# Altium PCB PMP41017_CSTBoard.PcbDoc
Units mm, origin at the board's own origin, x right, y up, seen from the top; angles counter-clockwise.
Board outline 22.5 x 35.13 mm, 4 copper layers (Top Layer, Layer 1, Layer 2, Bottom Layer), stack 1.926 mm thick; 6 components, 8 nets, 28 pads, 303 vias.
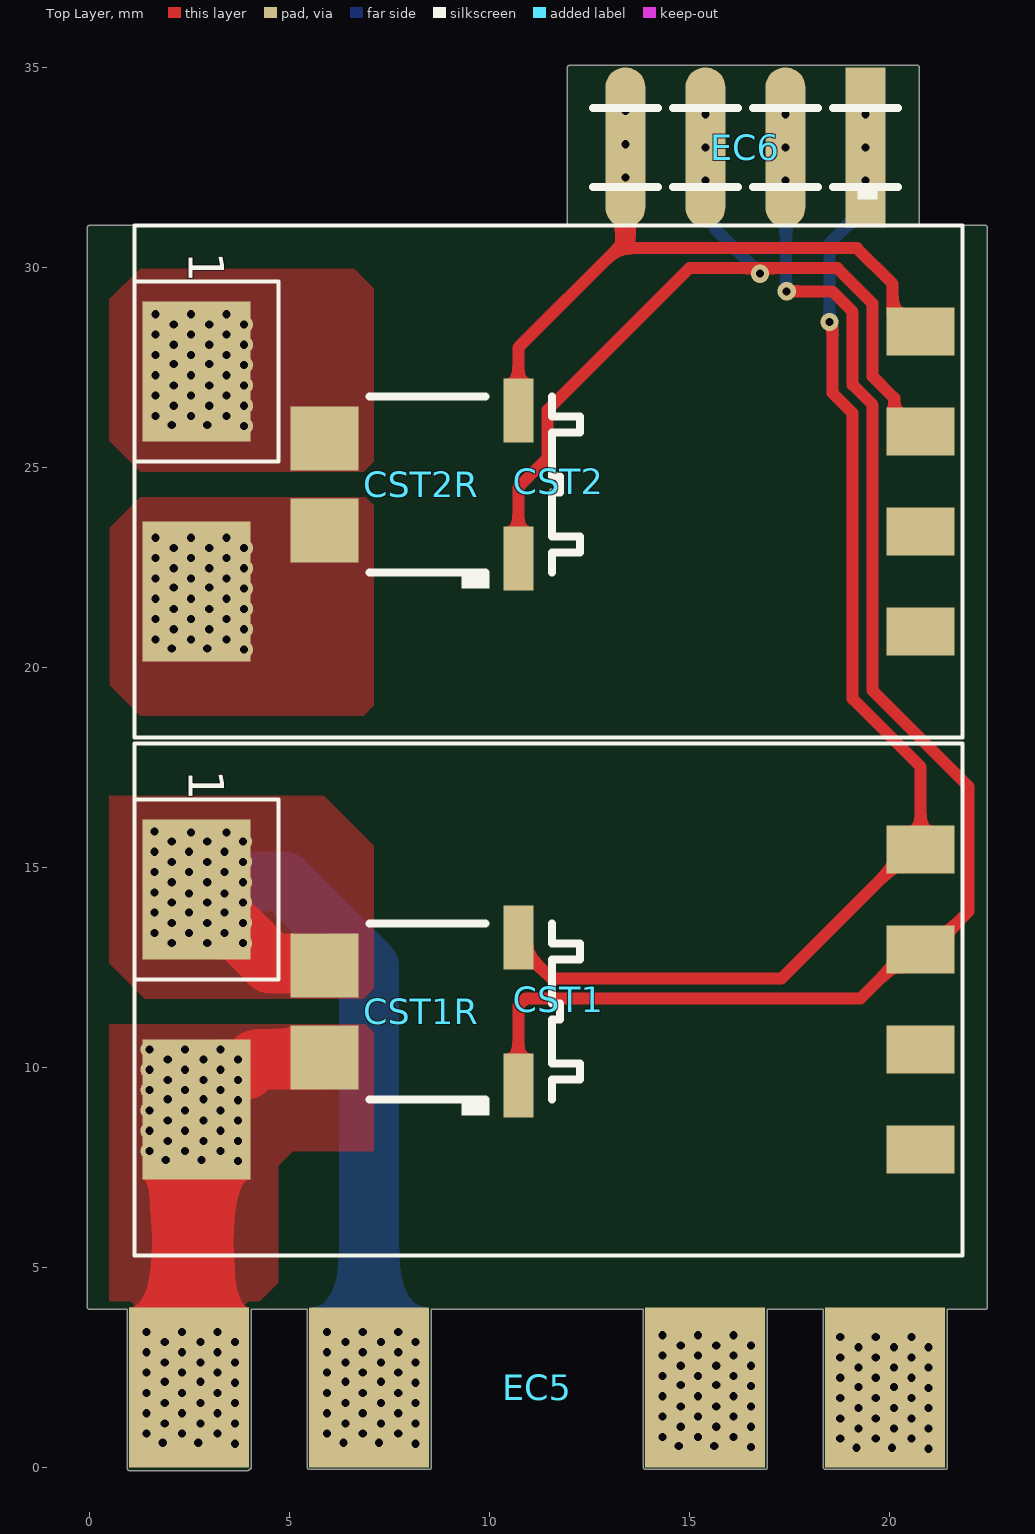
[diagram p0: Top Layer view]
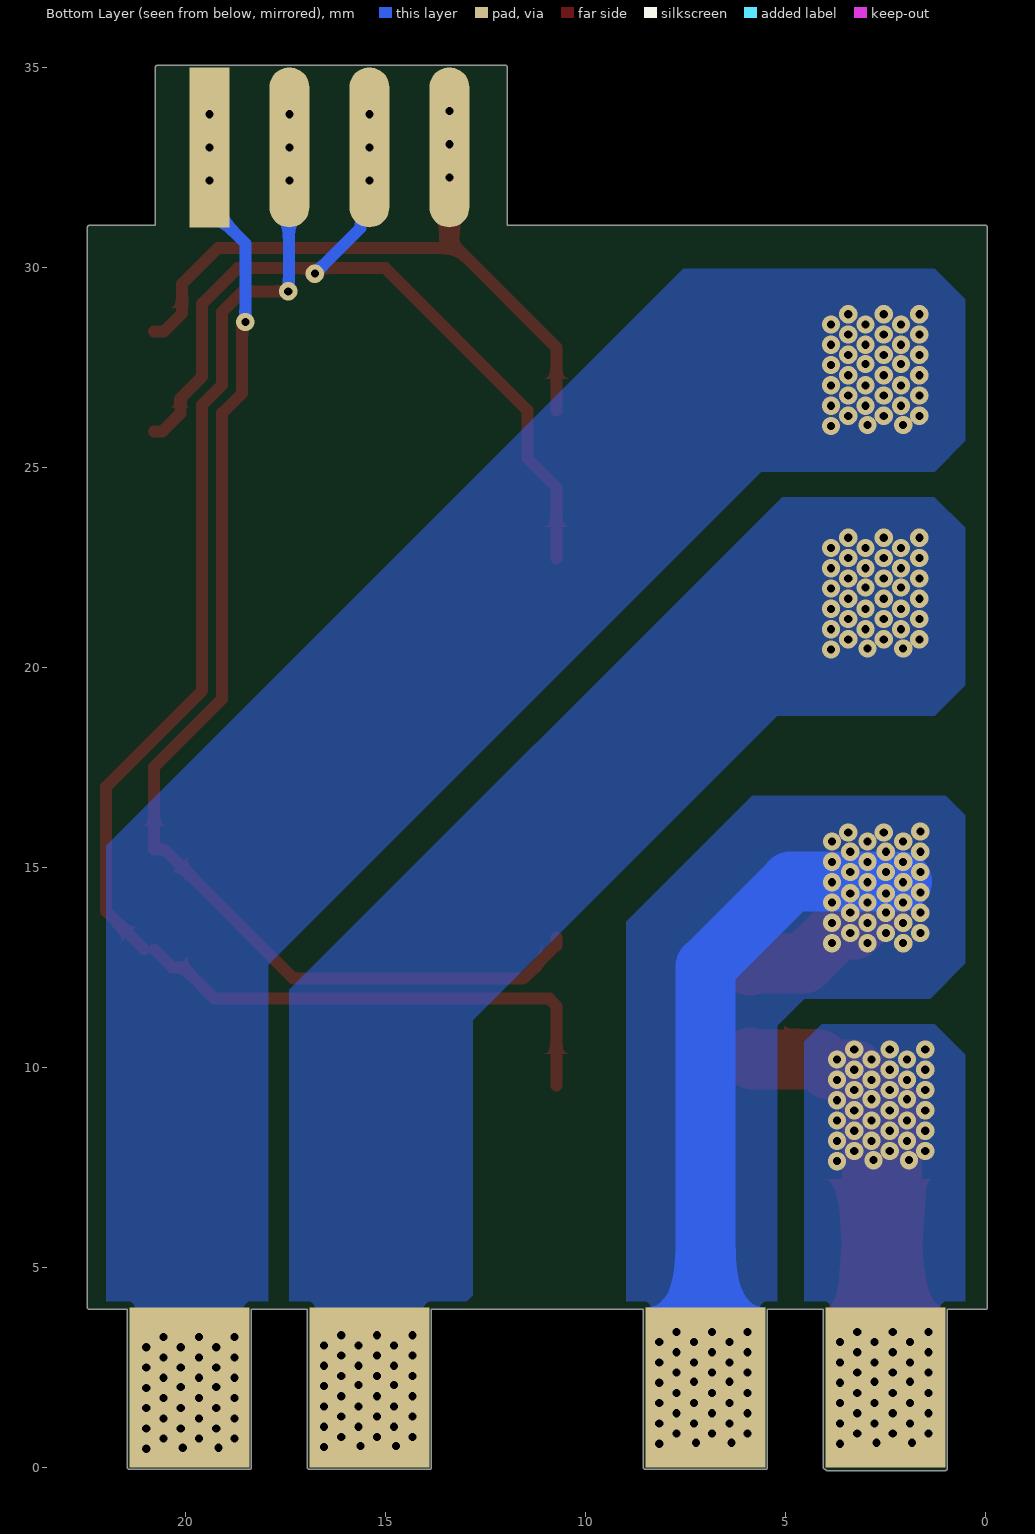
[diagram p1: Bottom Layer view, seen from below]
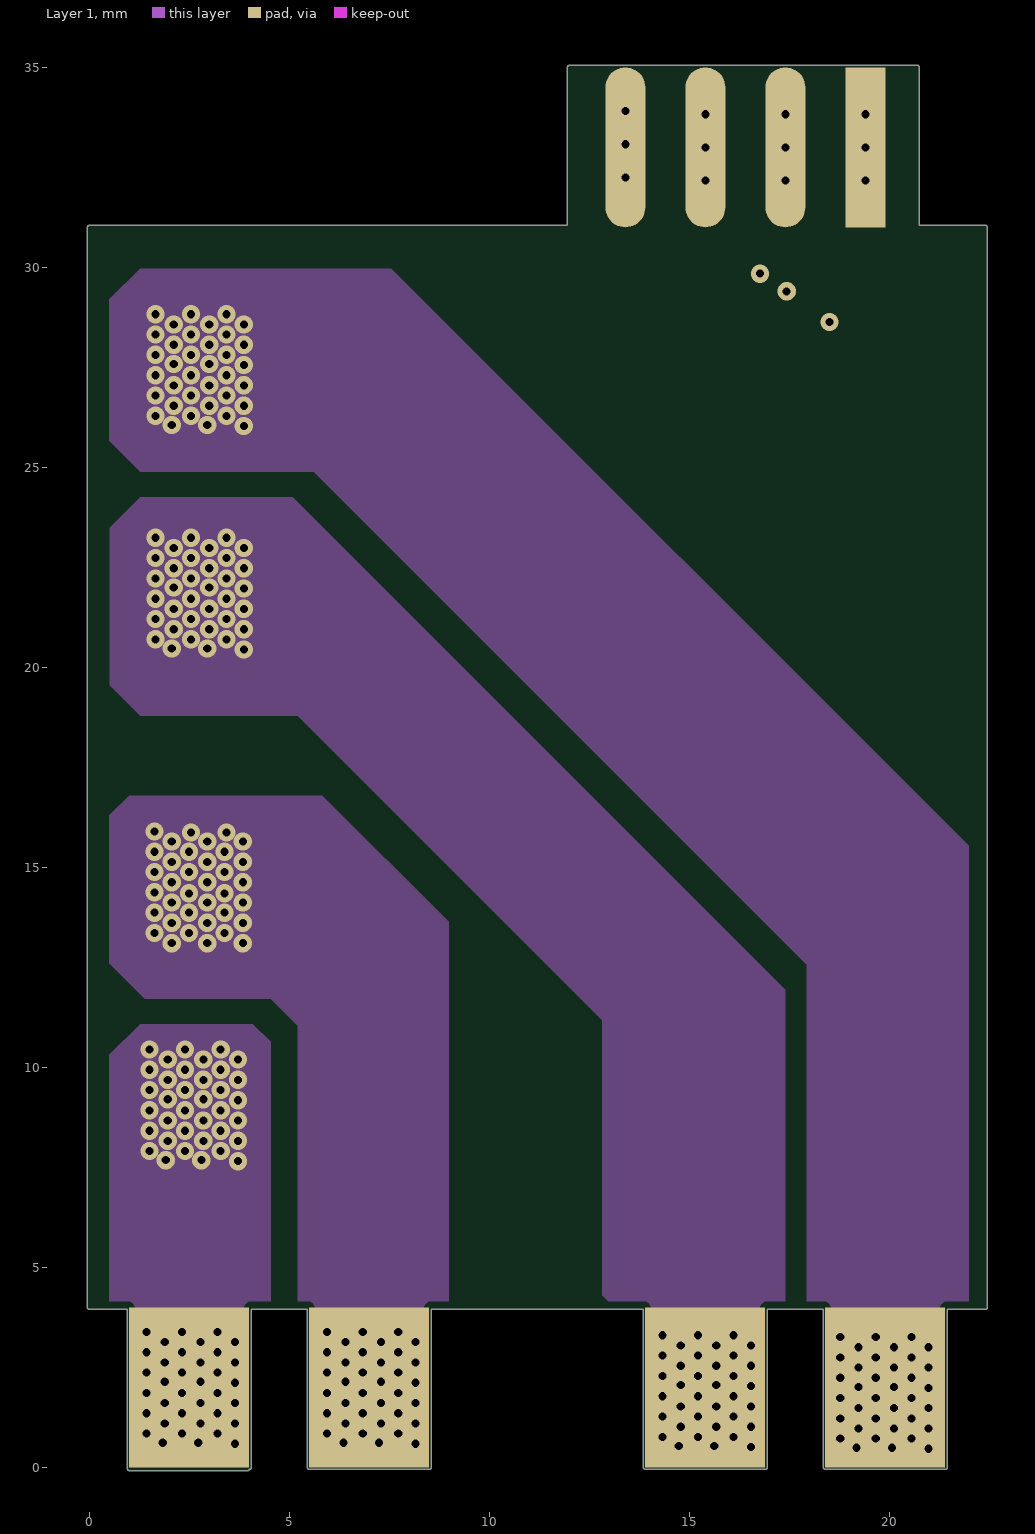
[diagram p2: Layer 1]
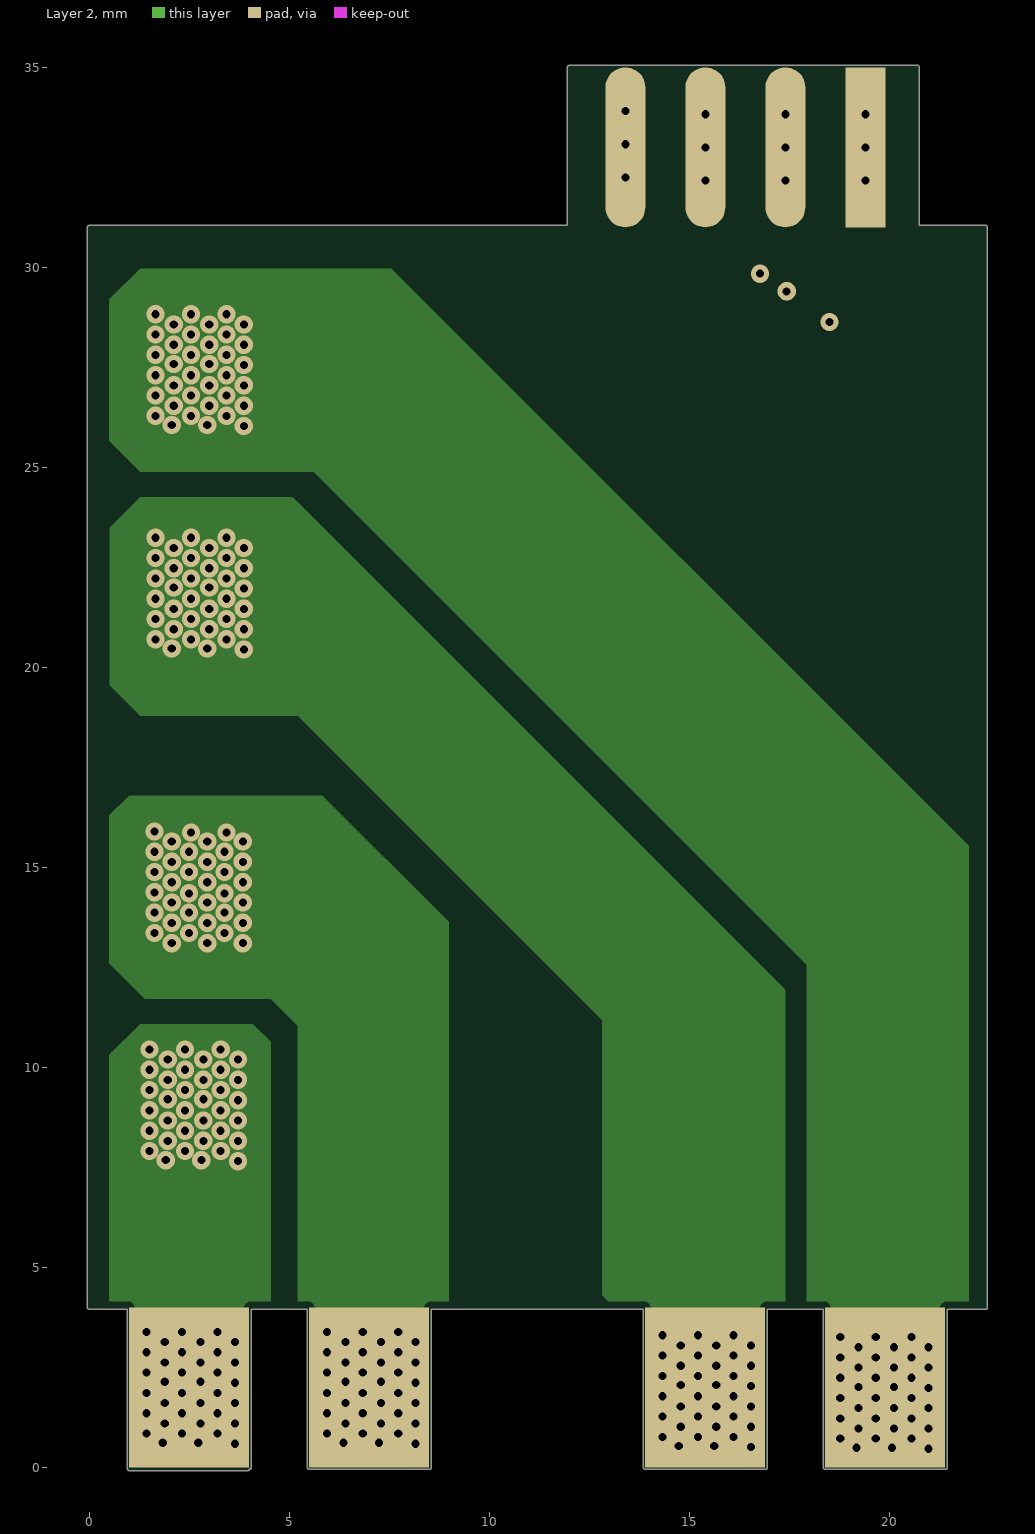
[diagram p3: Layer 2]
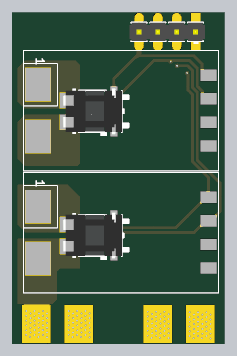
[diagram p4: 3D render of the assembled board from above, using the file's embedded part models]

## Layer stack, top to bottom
Top Solder: solder mask 0.0102, Solder Resist, Dk 3.5
Top Layer: signal copper 0.07
Dielectric 1: prepreg 0.0711, PP-006, Dk 4.1
Layer 1: signal copper 0.07
Dielectric1: core 1.5037, FR-4 High Tg, Dk 4.8
Layer 2: signal copper 0.07
Dielectric 2: prepreg 0.0711, PP-006, Dk 4.1
Bottom Layer: signal copper 0.07
Bottom Solder: solder mask 0.0102, Solder Resist, Dk 3.5

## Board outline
1,-0.079 3.957,-0.079 ccw(c3.957,-0.029) 4.003,-0.05 ccw(c4,0) 4.05,0 4.05,3.95 5.45,3.95 5.45,0 ccw(c5.5,0) 5.525,-0.044 ccw(c5.55,0) 5.55,-0.05 8.5,-0.05 ccw(c8.5,0) 8.55,0 8.55,3.95 13.85,3.95 13.85,0 ccw(c13.9,0) 13.9,-0.05 16.9,-0.05 ccw(c16.9,0) 16.95,0 16.95,3.95 18.35,3.95 18.35,0 ccw(c18.4,0) 18.4,-0.05 21.4,-0.05 ccw(c21.4,0) 21.45,0 21.45,3.95 22.4,3.95 ccw(c22.4,4) 22.45,4 22.45,31 ccw(c22.4,31) 22.4,31.05 20.75,31.05 20.75,35 ccw(c20.7,35) 20.7,35.05 12,35.05 ccw(c12,35) 11.95,35 11.95,31.05 0,31.05 ccw(c0,31) -0.05,31 -0.05,4 ccw(c0,4) 0,3.95 0.95,3.95 0.95,-0.029 ccw(c1,-0.029)

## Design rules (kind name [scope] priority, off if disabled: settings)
AcuteAngle [All] p1: minimum=4.50000000000000E+0001 checktracksonly=FALSE
AssemblyTestPointUsage [All] p1: valid=2
BoardOutlineClearance BoardOutlineClearance_MountingHoles [OnCopper and InComponentClass('Mounting Holes')] p1: gap=0.2 ignorepadtopadclearanceinfootprint=FALSE
BoardOutlineClearance BoardOutlineClearance_Poly [OnCopper and IsPoly] p2: gap=0.2 ignorepadtopadclearanceinfootprint=FALSE
BoardOutlineClearance [OnCopper and Not InComponentClass('Logo') and not InComponentClass('FiducialMark') and not InRegion(1000,500,4000,800) and not InPoly] p3: gap=0.2 ignorepadtopadclearanceinfootprint=FALSE
Clearance Clearance_Keepouts [((IsTrack Or IsArc) And Not InPoly) And IsFree and IsKeepOut vs ((IsTrack Or IsArc) And Not InPoly) And IsFree and IsKeepOut] p1: gap=0 ignorepadtopadclearanceinfootprint=FALSE
Clearance Clearance_Poly [InPolygon] p2: gap=0.254 ignorepadtopadclearanceinfootprint=TRUE
Clearance Clearance_FiducialMark [IsKeepOut and InComponentClass('FiducialMark') vs IsPad and InComponentClass('FiducialMark')] p3: gap=0 ignorepadtopadclearanceinfootprint=FALSE
Clearance [All] p4: gap=0.2 ignorepadtopadclearanceinfootprint=TRUE
ComponentClearance ComponentClearance_MountingHoles_FiducialMarks [InComponentClass('Mounting Holes') vs InComponentClass('FiducialMark')] p1 off: gap=1.27 collisioncheckmode=3 verticalgap=0.254 showdistances=FALSE
ComponentClearance ComponentClearance_Shunt [InComponentClass('Header') vs InComponentClass('Shunt')] p2 off: gap=0 collisioncheckmode=3 verticalgap=0 showdistances=FALSE
ComponentClearance ComponentClearance_Logo [InComponentClass('Logo')] p3 off: gap=0.762 collisioncheckmode=3 verticalgap=0.254 showdistances=FALSE
ComponentClearance ComponentClearance_ScrewToNut [(HasFootprint('NY PMS 440 0025 PH')) vs (HasFootprint('Keystone_1902C'))] p4 off: gap=0.127 collisioncheckmode=3 verticalgap=0.254 showdistances=FALSE
ComponentClearance ComponentClearance_MountingHoles [InComponentClass('Mounting Holes')] p5 off: gap=2.54 collisioncheckmode=3 verticalgap=2540 showdistances=FALSE
ComponentClearance ComponentClearance_SmallPassives [HasFootprint('0201*') or HasFootprint('0402*') or HasFootprint('0508') or HasFootprint('0603*') or HasFootprint('0612') or HasFootprint('0805*') or HasFootprint('0815*') or HasFootprint('0830*') or HasFootprint('1206*') or HasFootprint('1210*') or HasFootprint('1808*') or HasFootprint('1812*') or HasFootprint('1825*') or HasFootprint('2010*') or HasFootprint('2220*') or HasFootprint('2225*') or HasFootprint('2512*') or HasFootprint('2728*') or HasFootprint('3518*') vs HasFootprint('0201*') or HasFootprint('0402*') or HasFootprint('0508') or HasFootprint('0603*') or HasFootprint('0612') or HasFootprint('0805*') or HasFootprint('0815*') or HasFootprint('0830*') or HasFootprint('1206*') or HasFootprint('1210*') or HasFootprint('1808*') or HasFootprint('1812*') or HasFootprint('1825*') or HasFootprint('2010*') or HasFootprint('2220*') or HasFootprint('2225*') or HasFootprint('2512*') or HasFootprint('2728*') or HasFootprint('3518*')] p6 off: gap=0.38 collisioncheckmode=3 verticalgap=0.254 showdistances=FALSE
ComponentClearance ComponentClearance_THtoSMT [IsThruComponent vs IsSMTComponent] p7 off: gap=0.762 collisioncheckmode=3 verticalgap=0.762 showdistances=FALSE
ComponentClearance ComponentClearance_THtoTH [IsThruComponent vs IsThruComponent] p8 off: gap=0.508 collisioncheckmode=3 verticalgap=0.762 showdistances=FALSE
ComponentClearance [All] p9 off: gap=0.508 collisioncheckmode=3 verticalgap=0.254 showdistances=FALSE
DiffPairsRouting [All] p1: maxlimit=2.54 minlimit=0.254 mostfreqgap=0.254 toplayer_minwidth=0.381 toplayer_maxwidth=0.381 toplayer_prefwidth=0.381 midlayer1_minwidth=0.381 midlayer1_maxwidth=0.381 midlayer1_prefwidth=0.381 midlayer2_minwidth=0.381 midlayer2_maxwidth=0.381 midlayer2_prefwidth=0.381 bottomlayer_minwidth=0.381 bottomlayer_maxwidth=0.381 bottomlayer_prefwidth=0.381 maxuncoupledlength=25.4
FabricationTestPointUsage TestPointUsage [All] p1: valid=2 allowmultiple=FALSE
FabricationTestpoint Testpoint [All] p1: side=3 testpointundercomponent=TRUE minsize=1.016 maxsize=2.54 preferedsize=1.524 minholesize=0 maxholesize=1.016 preferedholesize=0.813 testpointgrid=0.025 allowsidetop=TRUE allowsidebottom=TRUE usegrid=TRUE gridtolerance=0
FanoutControl Fanout_LCC [IsLCC] p1: bgadir=Out bgaviamode=Centered fanoutstyle=Auto fanoutdirection=Alternating viagrid=0.025 // Fanout_LCC (Default Rule)
FanoutControl Fanout_BGA [IsBGA] p2: bgadir=Out bgaviamode=Centered fanoutstyle=Auto fanoutdirection=Alternating viagrid=0.025 // Fanout_BGA (Default Rule)
FanoutControl Fanout_Default [All] p4: bgadir=Out bgaviamode=Centered fanoutstyle=Auto fanoutdirection=Alternating viagrid=0.025 // Fanout_Default (Default Rule)
FanoutControl Fanout_Small [(CompPinCount < 5)] p5: bgadir=Out bgaviamode=Centered fanoutstyle=Auto fanoutdirection=OutThenIn viagrid=0.025 // Fanout_Small (Default Rule)
Height [All] p1 off: minheight=0 maxheight=30 prefheight=12.7
HoleSize [All] p1: absolutevalues=TRUE maxlimit=6.375 minlimit=0.2 maxpercent=80.000 minpercent=20.000
MinimumAnnularRing MinimumAnnularRing_ThermalPadVias [IsVia and InAnyComponent] p1: minimumring=0.15
MinimumAnnularRing [All] p2: minimumring=0.2
MinimumSolderMaskSliver MinimumSolderMaskSliver_Logo [InComponentClass('Logo') vs InComponentClass('Logo')] p1: minsoldermaskwidth=0.018
MinimumSolderMaskSliver [All] p2: minsoldermaskwidth=0.1
PlaneConnect [All] p1: planeconnectstyle=Direct reliefexpansion=0.254 reliefentries=4 reliefconductorwidth=0.254 reliefairgap=0.254
PolygonConnect [All] p1: connectstyle=Direct reliefconductorwidth=0.254 reliefentries=4 polygonreliefangle="90 Angle" airgapwidth=0.254
RoutingVias ThermalPadVias [IsVia and InAnyComponent] p1: holewidth=0.2 width=0.5 viastyle="Through Hole" minholewidth=0.2 minwidth=0.5 maxholewidth=0.33 maxwidth=0.6
RoutingVias [All] p2: holewidth=0.3 width=0.5 viastyle="Through Hole" minholewidth=0.2 minwidth=0.61 maxholewidth=1.016 maxwidth=1.651
SilkToBoardRegionClearance [Not ((IsComment or IsDesignator) And (Hide <> 'False')) and not InRegion(1000,500,4000,800)] p1:
SilkToSilkClearance SilkToSilkClearance_Pb-FreeLogo [(HasFootprint('Pb-Free_Overlay_Medium') OR HasFootprint('Pb-Free_Overlay_Small')) vs (HasFootprint('Pb-Free_Overlay_Medium') OR HasFootprint('Pb-Free_Overlay_Small'))] p1: silktosilkclearance=0
SilkToSilkClearance [All] p2: silktosilkclearance=0.1
SilkToSolderMaskClearance SilkToComponentPadClearance [(IsPad or IsFill or IsRegion) and InAnycomponent] p1: minsilkscreentomaskgap=0.127 clearancetoexposedcopper=TRUE
SilkToSolderMaskClearance "Silk to Solder Mask Opening" [All] p2: minsilkscreentomaskgap=0.1 clearancetoexposedcopper=FALSE
SolderMaskExpansion [All] p1: expansion=0.05 istentingtop=FALSE
UnRoutedNet [All] p1: checkbadconnections=TRUE
Width [All] p1: maxlimit=2.54 minlimit=0.152 preferedwidth=0.254 checkconnectedcopper=TRUE
13 further rules are at their usual default settings.

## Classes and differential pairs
component class Header: EC6

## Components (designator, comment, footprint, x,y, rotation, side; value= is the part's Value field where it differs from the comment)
CST1 "PAS6322.050NLT" Pulse_PAS6322 11.731,11.7 r270 top locked
CST1R "CST7030-050LC" Coilcraft_CST7030 8.3,11.4 r180 top
CST2 "PAS6322.050NLT" Pulse_PAS6322 11.731,24.65 r270 top locked
CST2R "CST7030-050LC" Coilcraft_CST7030 8.3,24.575 r180 top
EC5 "Edge Finger" EC_CST 22.494,3.95 r180 top
EC6 "PTT-104-01-L-S" Samtec_PTT-104-01-x-S 16.4,33 r180 top locked

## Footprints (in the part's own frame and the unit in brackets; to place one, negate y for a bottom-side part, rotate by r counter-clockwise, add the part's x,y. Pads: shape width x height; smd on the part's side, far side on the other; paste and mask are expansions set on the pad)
Coilcraft_CST7030 [mm] "SMD, 4-Leads, Body 7x5.2mm"
  rect 0.75x1.6 smd: 1(-2.425,1.85) 2(-2.425,-1.85)
  rect 1.7x1.6 smd: 3(2.425,-1.15) 4(2.425,1.15)
  silkscreen extent -3.97,-2.2 1.3,2.6, body extent -3.97,-2.5 3.03,2.5, height 3
EC_CST [mm] "Edge connector of HB LLC GaN DC"
  rect 3x4 all layers, no hole: 1(2.6,1.95) 2(7.1,1.95) 3(15.5,1.95) 4(20,1.95)
Pulse_PAS6322 [mm]
  rect 3.5x2.7 smd: 1(-2.75,-9.05) 2(2.75,-9.05)
  rect 1.2x1.7 smd: 3(3.75,9.05) 4(1.25,9.05) 5(-1.25,9.05) 6(-3.75,9.05)
  silkscreen extent -6.4,-10.6 6.4,10.1
Samtec_PTT-104-01-x-S [mm] "Header, 2mm, 4x1, TH"
  rect 1x4 all layers, no hole: 1(-3,0)
  oval 1x4 all layers, no hole: 2(-1,0) 3(1,0) 4(3,0)
  silkscreen extent -3.81,-0.99 3.81,1.3, body extent -4,-0.99 4,0.99, height 4.7

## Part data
CST1 CST2: library part Coilcraft_CST7030, "Current Sense Transformer, 1100uH, SMT", Manufacturer=Pulse
CST1R CST2R: library part CMP-0030157-2, "Current Sense Transformer, 333uH, SMT", Manufacturer=Coilcraft
EC5: library part EC_CT, "Edge Finger of CT board"
EC6: library part CMP-0055572-1, "Header, 2mm, 4x1, Gold, TH", Color=Black, Current_A=2.9A, Manufacturer=Samtec

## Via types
v1: diameter 0.457, hole 0.203, Top Layer to Bottom Layer, tented both sides, 303 vias

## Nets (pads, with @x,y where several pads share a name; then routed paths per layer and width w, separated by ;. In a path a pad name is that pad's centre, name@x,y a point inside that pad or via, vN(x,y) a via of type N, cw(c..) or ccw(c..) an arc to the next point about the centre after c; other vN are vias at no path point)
CT1p_in: CST1.2 CST1R.4 EC5.4 | length 11
  Top Layer w1.5: CST1.2@2.587,8.857 2.587,9.257 3.281,9.95 3.909,9.95 4.159,10.2 5.825,10.2 CST1R.4
  Top Layer w2: EC5.4 2.587,2.093 CST1.2@2.587,8.857
  other v1: 3.636,0.592 1.833,0.617 2.722,0.617 1.426,0.846 2.315,0.846 3.204,0.846 1.884,1.1 2.773,1.1 3.636,1.1 1.426,1.354 2.315,1.354 3.204,1.354 1.884,1.608 2.773,1.608 3.636,1.608 1.426,1.862 2.315,1.862 3.204,1.862 3.636,2.116 1.884,2.141 2.773,2.141 1.426,2.37 2.315,2.37 3.204,2.37 1.884,2.624 2.773,2.624 3.636,2.624 1.426,2.878 2.315,2.878 3.204,2.878 1.884,3.132 2.773,3.132 3.636,3.132 1.426,3.386 2.315,3.386 3.204,3.386 3.712,7.656 1.909,7.681 2.798,7.681 1.503,7.91 2.392,7.91 3.281,7.91 1.96,8.164 2.849,8.164 3.712,8.164 1.503,8.418 2.392,8.418 3.281,8.418 1.96,8.672 2.849,8.672 3.712,8.672 1.503,8.926 2.392,8.926 3.281,8.926 3.712,9.18 1.96,9.205 2.849,9.205 1.503,9.434 2.392,9.434 3.281,9.434 1.96,9.688 2.849,9.688 3.712,9.688 1.503,9.942 2.392,9.942 3.281,9.942 1.96,10.196 2.849,10.196 3.712,10.196 1.503,10.45 2.392,10.45 3.281,10.45
CT1p_out: CST1.1 CST1R.3 EC5.3 | length 20.1
  Top Layer w1.5: CST1.1@2.681,14.05 3.281,13.45 3.681,13.45 4.531,12.6 5.825,12.6 CST1R.3
  Bottom Layer w1.5: v1@2.083,14.643 4.869,14.643 6.994,12.518 EC5.3
  other v1: 8.153,0.592 6.35,0.617 7.239,0.617 5.944,0.846 6.833,0.846 7.722,0.846 6.401,1.1 7.29,1.1 8.153,1.1 5.944,1.354 6.833,1.354 7.722,1.354 6.401,1.608 7.29,1.608 8.153,1.608 5.944,1.862 6.833,1.862 7.722,1.862 8.153,2.116 6.401,2.141 7.29,2.141 5.944,2.37 6.833,2.37 7.722,2.37 6.401,2.624 7.29,2.624 8.153,2.624 5.944,2.878 6.833,2.878 7.722,2.878 6.401,3.132 7.29,3.132 8.153,3.132 5.944,3.386 6.833,3.386 7.722,3.386 2.057,13.106 2.946,13.106 3.835,13.106 1.626,13.36 2.489,13.36 3.378,13.36 2.057,13.614 2.946,13.614 3.835,13.614 1.626,13.868 2.489,13.868 3.378,13.868 2.057,14.122 2.946,14.122 3.835,14.122 2.489,14.351 3.378,14.351 1.626,14.376 2.057,14.63 2.946,14.63 3.835,14.63 1.626,14.884 2.489,14.884 3.378,14.884 2.057,15.138 2.946,15.138 3.835,15.138 1.626,15.392 2.489,15.392 3.378,15.392 2.057,15.646 2.946,15.646 3.835,15.646 2.54,15.875 3.429,15.875 1.626,15.9
CT1s_neg: CST1.5 CST1R.1 EC6.2 | length 35.6
  Top Layer w0.3: CST1R.1 10.725,11.541 10.901,11.717 19.273,11.717 20.056,12.5 20.331,12.5 CST1.5 ; v1(17.43,29.401) 18.568,29.401 19.081,28.888 19.081,27.066 19.581,26.566 19.581,19.42 21.981,17.02 21.981,13.9 CST1.5@21.031,12.95
  Bottom Layer w0.3: v1(17.4,33) v1(17.4,32.17) 17.415,32.155 17.415,29.416 v1(17.43,29.401)
  other v1: 17.4,33.829
CT1s_pos: CST1.6 CST1R.2 EC6.1 | length 30.8
  Top Layer w0.3: CST1R.2 10.725,13.05 11.558,12.217 17.297,12.217 20.081,15 20.531,15.45 CST1.6 20.781,17.513 19.081,19.213 19.081,26.358 18.581,26.858 18.581,28.515 18.502,28.594 v1(18.502,28.636)
  Bottom Layer w0.3: v1(18.502,28.636) 18.502,30.602 19.4,31.5 v1(19.4,33)
  other v1: 19.4,32.17 19.4,33.829
CT2p_in: CST2.1 CST2R.3 EC5.1
  other v1: 20.98,0.465 19.177,0.49 20.066,0.49 18.771,0.719 19.66,0.719 20.549,0.719 19.228,0.973 20.117,0.973 20.98,0.973 18.771,1.227 19.66,1.227 20.549,1.227 19.228,1.481 20.117,1.481 20.98,1.481 18.771,1.735 19.66,1.735 20.549,1.735 20.98,1.989 19.228,2.014 20.117,2.014 18.771,2.243 19.66,2.243 20.549,2.243 19.228,2.497 20.117,2.497 20.98,2.497 18.771,2.751 19.66,2.751 20.549,2.751 19.228,3.005 20.117,3.005 20.98,3.005 18.771,3.259 19.66,3.259 20.549,3.259 3.861,26.035 2.057,26.06 2.946,26.06 1.651,26.289 2.54,26.289 3.429,26.289 2.108,26.543 2.997,26.543 3.861,26.543 1.651,26.797 2.54,26.797 3.429,26.797 2.108,27.051 2.997,27.051 3.861,27.051 1.651,27.305 2.54,27.305 3.429,27.305 3.861,27.559 2.108,27.584 2.997,27.584 1.651,27.813 2.54,27.813 3.429,27.813 2.108,28.067 2.997,28.067 3.861,28.067 1.651,28.321 2.54,28.321 3.429,28.321 2.108,28.575 2.997,28.575 3.861,28.575 1.651,28.829 2.54,28.829 3.429,28.829
CT2p_out: CST2.2 CST2R.4 EC5.2
  other v1: 16.535,0.51 14.732,0.535 15.621,0.535 14.326,0.764 15.215,0.764 16.104,0.764 14.783,1.018 15.672,1.018 16.535,1.018 14.326,1.272 15.215,1.272 16.104,1.272 14.783,1.526 15.672,1.526 16.535,1.526 14.326,1.78 15.215,1.78 16.104,1.78 16.535,2.034 14.783,2.059 15.672,2.059 14.326,2.288 15.215,2.288 16.104,2.288 14.783,2.542 15.672,2.542 16.535,2.542 14.326,2.796 15.215,2.796 16.104,2.796 14.783,3.05 15.672,3.05 16.535,3.05 14.326,3.304 15.215,3.304 16.104,3.304 3.861,20.447 2.057,20.472 2.946,20.472 1.651,20.701 2.54,20.701 3.429,20.701 2.108,20.955 2.997,20.955 3.861,20.955 1.651,21.209 2.54,21.209 3.429,21.209 2.108,21.463 2.997,21.463 3.861,21.463 1.651,21.717 2.54,21.717 3.429,21.717 3.861,21.971 2.108,21.996 2.997,21.996 1.651,22.225 2.54,22.225 3.429,22.225 2.108,22.479 2.997,22.479 3.861,22.479 1.651,22.733 2.54,22.733 3.429,22.733 2.108,22.987 2.997,22.987 3.861,22.987 1.651,23.241 2.54,23.241 3.429,23.241
CT2s_neg: CST2.6 CST2R.2 EC6.4 | length 16.5
  Top Layer w0.3: CST2R.2 10.725,27.997 13.208,30.48 ; 13.4,30.672 13.208,30.48 ; CST2.6 20.531,28.4 20.081,28.85 20.081,29.587 19.188,30.48 13.208,30.48
  Top Layer w0.5: 13.4,30.672 EC6.4
  other v1: 13.4,32.25 13.4,33.079 13.4,33.909
CT2s_pos: CST2.5 CST2R.1 EC6.3 | length 21.5
  Top Layer w0.3: CST2R.1 10.725,24.504 11.45,25.229 11.45,26.431 14.999,29.98 16.764,29.98 18.696,29.98 19.581,29.096 19.581,27.273 20.124,26.73 20.124,26.35 20.574,25.9 CST2.5
  Bottom Layer w0.3: v1(15.4,33) 15.4,31.311 15.626,31.084 15.626,30.983 v1(16.764,29.845)
  other v1: 15.4,32.17 15.4,33.829
pads on no net: CST1.3 CST1.4 CST2.3 CST2.4

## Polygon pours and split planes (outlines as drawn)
CT1p_out on Top Layer "TOP_LAYER_CT1P_OUT_P002" (solid, remove dead copper, pour order 2): 0.5,16.797 0.5,12.6 1.383,11.717 6.858,11.717 7.112,11.971 7.112,15.546 5.861,16.797
CT1p_in on Top Layer "TOP_LAYER_CT1P_IN_P003" (solid, remove dead copper, pour order 3): 3.815,3.714 4.717,4.617 4.717,7.547 5.08,7.91 7.112,7.91 7.112,10.875 6.905,11.082 0.5,11.082 0.5,3.714
CT2p_out on Top Layer "TOP_LAYER_CT2P_OUT_P001" (solid, remove dead copper, pour order 1): 0.508,19.558 0.508,23.492 1.273,24.257 6.905,24.257 7.112,24.05 7.112,19.05 6.858,18.796 1.27,18.796
CT2p_in on Top Layer "TOP_LAYER_CT2P_IN_P000" (solid, remove dead copper, pour order 0): 0.5,25.662 0.5,29.202 1.27,29.972 6.618,29.972 7.112,29.478 7.112,25.146 6.858,24.892 1.27,24.892
CT2p_in on Bottom Layer "BOTTOM_LAYER_CT2P_IN_P007" (solid, remove dead copper, pour order 7): 1.27,24.892 5.602,24.892 17.93,12.564 17.93,4.099 18.4,3.63 21.61,3.63 21.981,4 21.981,15.541 7.55,29.972 1.27,29.972 0.5,29.202 0.5,25.662
CT2p_out on Bottom Layer "BOTTOM_LAYER_CT2P_OUT_P006" (solid, remove dead copper, pour order 6): 1.27,18.796 5.204,18.796 12.817,11.183 12.817,4.305 13.863,3.259 16.659,3.259 17.4,4 17.4,11.937 5.08,24.257 1.273,24.257 0.508,23.492 0.508,19.558
CT1p_out on Bottom Layer "BOTTOM_LAYER_CT1P_OUT_P005" (solid, remove dead copper, pour order 5): 0.5,12.6 1.383,11.717 4.53,11.717 5.207,11.04 5.207,3.793 5.5,3.5 8.653,3.5 8.982,3.829 8.982,13.64 5.825,16.797 0.994,16.797 0.5,16.303
CT1p_in on Bottom Layer "BOTTOM_LAYER_CT1P_IN_P004" (solid, remove dead copper, pour order 4): 1.27,11.082 4.088,11.082 4.531,10.639 4.531,4 3.96,3.429 1,3.429 1,3.5 0.5,4 0.5,10.312
CT2p_in on Layer 2 "LAYER_2_CT2P_IN_P011" (solid, remove dead copper, pour order 11): 1.27,24.892 5.602,24.892 17.93,12.564 17.93,4.099 18.4,3.63 21.61,3.63 21.981,4 21.981,15.541 7.55,29.972 1.27,29.972 0.5,29.202 0.5,25.662
CT2p_out on Layer 2 "LAYER_2_CT2P_OUT_P010" (solid, remove dead copper, pour order 10): 1.27,18.796 5.204,18.796 12.817,11.183 12.817,4.305 13.863,3.259 16.659,3.259 17.4,4 17.4,11.937 5.08,24.257 1.273,24.257 0.508,23.492 0.508,19.558
CT1p_out on Layer 2 "LAYER_2_CT1P_OUT_P009" (solid, remove dead copper, pour order 9): 0.5,12.6 1.383,11.717 4.53,11.717 5.207,11.04 5.207,3.793 5.5,3.5 8.653,3.5 8.982,3.829 8.982,13.64 5.825,16.797 0.994,16.797 0.5,16.303
CT1p_in on Layer 2 "LAYER_2_CT1P_IN_P008" (solid, remove dead copper, pour order 8): 1.27,11.082 4.088,11.082 4.531,10.639 4.531,4 3.96,3.429 1,3.429 1,3.5 0.5,4 0.5,10.312
CT2p_in on Layer 1 "LAYER_1_CT2P_IN_P015" (solid, remove dead copper, pour order 15): 1.27,24.892 5.602,24.892 17.93,12.564 17.93,4.099 18.4,3.63 21.61,3.63 21.981,4 21.981,15.541 7.55,29.972 1.27,29.972 0.5,29.202 0.5,25.662
CT2p_out on Layer 1 "LAYER_1_CT2P_OUT_P014" (solid, remove dead copper, pour order 14): 1.27,18.796 5.204,18.796 12.817,11.183 12.817,4.305 13.863,3.259 16.659,3.259 17.4,4 17.4,11.937 5.08,24.257 1.273,24.257 0.508,23.492 0.508,19.558
CT1p_out on Layer 1 "LAYER_1_CT1P_OUT_P013" (solid, remove dead copper, pour order 13): 0.5,12.6 1.383,11.717 4.53,11.717 5.207,11.04 5.207,3.793 5.5,3.5 8.653,3.5 8.982,3.829 8.982,13.64 5.825,16.797 0.994,16.797 0.5,16.303
CT1p_in on Layer 1 "LAYER_1_CT1P_IN_P012" (solid, remove dead copper, pour order 12): 1.27,11.082 4.088,11.082 4.531,10.639 4.531,4 3.96,3.429 1,3.429 1,3.5 0.5,4 0.5,10.312

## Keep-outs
Keep-Out Layer:
  text ".Layer_Name" at -20.343,-59.464 h1.52

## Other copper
Top Layer:
  text ".Layer_Name" at -20.343,-59.464 h1.52
Bottom Layer:
  text ".Layer_Name" at -20.343,-59.464 h1.52

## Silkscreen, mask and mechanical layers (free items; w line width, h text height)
Top Overlay:
  text "'.PRJ_Number'.PCB_Rev" at 116.739,-34.38 h2.75
  text ".Layer_Name" at -20.343,-59.464 h1.52
Bottom Overlay:
  text ".Layer_Name" at -20.343,-59.464 h1.52
Top Paste:
  text ".Layer_Name" at -20.343,-59.464 h1.52
Bottom Paste:
  text ".Layer_Name" at -20.343,-59.464 h1.52
Top Solder:
  text ".Layer_Name" at -20.343,-59.464 h1.52
  text ".Layer_Name" at -20.343,-59.464 h1.52
Bottom Solder:
  text ".Layer_Name" at -20.343,-59.464 h1.52
Drill Guide:
  text ".Layer_Name" at -20.343,-59.464 h1.52
M1 Board Outline:
  lines w0.1: 3.957,-0.029 1,-0.029 1,0 1,4 0,4 0,31 12,31 12,35 20.7,35 20.7,31 22.4,31 22.4,4 21.4,4 21.4,0 18.4,0 18.4,4 16.9,4 16.9,0 13.9,0 13.9,4 8.5,4 8.5,0 5.55,0 ; 5.5,0 5.5,4 4,4 ; 4,4 4,0 4,4
  text ".Layer_Name" at -20.343,-59.464 h1.52
M2 Board Dimensions:
  rectangle: -34.999,-44.643 -31.824,-41.468
  rectangle: -31.824,-47.818 -22.299,-44.643
  lines w0.178: -34.999,-44.643 -9.599,-44.643 ; -31.824,-47.818 -31.824,-41.468 ; -28.649,-47.818 -28.649,-41.468 ; -22.299,-47.818 -22.299,-41.468 ; -15.949,-47.818 -15.949,-41.468 ; -34.999,-47.818 -9.599,-47.818 -9.599,-41.468 -34.999,-41.468 -34.999,-47.818
  text ".Layer_Name" at -20.343,-59.464 h1.52
M3 3D STEP Top:
  text ".Layer_Name" at -20.343,-59.464 h1.52
M4 3D STEP Bottom:
  text ".Layer_Name" at -20.343,-59.464 h1.52
M5 Assembly Top:
  lines w0.254: -42.416,-61.285 125.224,-61.285 ; -42.416,-56.12 125.275,-56.12 ; -42.416,-50.955 -42.416,-66.449 59.311,-66.449 125.275,-66.449 125.275,-50.955 -42.403,-50.955 -42.403,-66.449 -2.386,-66.449 ; 20.195,-66.449 20.195,-50.955 ; 52.377,-56.12 52.377,-50.955 ; 73.713,-56.12 73.713,-50.955 ; 89.512,-66.614 89.512,-61.463
  text "COMPONENTS MARKED 'DNP' SHOULD NOT BE POPULATED." at -5.7,-45.748 h1.52
  text "ASSEMBLY VARIANT:" at -5.713,-48.682 h1.52
  text ".VariantName" at 20.601,-48.682 h1.52
  text "PCB VIEWED FROM TOP SIDE" at -40.803,-54.312 h1.52
  text "BOARD #:" at 22.1,-54.312 h1.52
  text ".PRJ_Number" at 35.956,-54.312 h1.52
  text "REV:" at 57.406,-54.312 h1.52
  text ".PCB_Rev" at 64.81,-54.312 h1.52
  text "SVN REV:" at 78.691,-54.312 h1.52
  text ".VersionControl_RevNumber" at 91.544,-54.312 h1.52
  text "TID #:" at 22.1,-59.477 h1.52
  text ".TID" at 35.956,-59.477 h1.52
  text "PLOT NAME =" at -40.803,-64.693 h1.52
  text ".plot_File_Name" at -20.343,-64.693 h1.52
  text "GENERATED    :" at 22.151,-64.693 h1.52
  text ".Print_Date" at 44.236,-64.693 h1.52
  text ".Print_Time" at 62.753,-64.693 h1.52
  text "TEXAS INSTRUMENTS" at 94.871,-64.693 h1.52
M6 Assembly Bottom:
  lines w0.254: -42.429,-56.133 125.262,-56.133 ; -42.378,-61.297 125.262,-61.297 ; -6.665,-66.627 -6.665,-61.475 ; 9.133,-56.133 9.133,-50.968 ; 30.469,-56.133 30.469,-50.968 ; 62.651,-66.462 62.651,-50.968 ; 85.232,-66.462 125.249,-66.462 125.249,-50.968 -42.429,-50.968 -42.429,-66.462 23.535,-66.462 125.262,-66.462 125.262,-50.968
  text "COMPONENTS MARKED 'DNP' SHOULD NOT BE POPULATED." at 119.992,-45.736 h1.52
  text ".VariantName" at 93.474,-48.682 h1.52
  text "ASSEMBLY VARIANT:" at 119.865,-48.682 h1.52
  text ".VersionControl_RevNumber" at -8.697,-54.325 h1.52
  text "SVN REV:" at 4.155,-54.325 h1.52
  text ".PCB_Rev" at 18.036,-54.325 h1.52
  text "REV:" at 25.44,-54.325 h1.52
  text ".PRJ_Number" at 46.89,-54.325 h1.52
  text "BOARD #:" at 60.746,-54.325 h1.52
  text "PCB VIEWED FROM BOTTOM SIDE" at 123.649,-54.325 h1.52
  text ".TID" at 46.89,-59.49 h1.52
  text "TID #:" at 60.746,-59.49 h1.52
  text "TEXAS INSTRUMENTS" at -12.025,-64.705 h1.52
  text ".Print_Time" at 20.093,-64.705 h1.52
  text ".Print_Date" at 38.61,-64.705 h1.52
  text "GENERATED    :" at 60.695,-64.705 h1.52
  text ".plot_File_Name" at 103.19,-64.705 h1.52
  text "PLOT NAME =" at 123.649,-64.705 h1.52
M7 LPKF Text Top:
  lines w6: 15.619,7.027 22,6.975
M9 Title Sheet:
  drawing of 57 lines, arcs and shapes, not listed
  text "1" at -16.207,166.469 h1.78
  text "2" at 47.183,166.469 h1.78
  text "3" at 110.412,166.469 h1.78
  text "4" at 174.081,166.469 h1.78
  text "5" at 237.556,166.469 h1.78
  text "6" at 301.183,166.469 h1.78
  text "A" at -45.578,137.436 h1.78
  text "A" at 330.342,137.436 h1.78
  text "B" at -45.578,76.984 h1.78
  text "B" at 330.342,76.984 h1.78
  text "C" at -45.578,16.659 h1.78
  text "C" at 330.342,16.659 h1.78
  text "PROJECT TITLE:" at 253.126,-30.61 h1.14
  text ".PRJ_Title" at 254.396,-33.996 h1.78
  text "DESIGNED FOR:" at 253.126,-38.255 h1.14
  text ".PRJ_Customer" at 254.396,-41.811 h1.78
  text "D" at -45.578,-43.539 h1.78
  text "D" at 330.342,-43.539 h1.78
  text "FILE NAME:" at 253.126,-45.875 h1.14
  text ".PCB_File_Name_No_Path" at 254.396,-48.923 h1.78
  text "Texas Instruments (TI) and/or its licensors do not warrant the accuracy or completeness of this specification" at 126.9,-53.034 h1.14
  text "ENGINEER:" at 253.126,-53.241 h1.14
  text "LAYOUT BY:" at 291.353,-53.241 h1.14
  text "or any information contained therein. TI and/or its licensors do not warrant that this design will meet" at 125.758,-55.896 h1.14
  text ".PRJ_Engineer" at 254.396,-57.178 h1.78
  text ".PCB_Layout" at 292.635,-57.178 h1.78
  text "the specifications, will be suitable for your application or fit for any particular purpose, or will operate in" at 125.758,-58.757 h1.14
  text ".Layer_Name" at -20.343,-59.464 h1.52
  text "ALTIUM DESIGNER VERSION:" at 291.353,-61.115 h1.14
  text "an implementation. TI and/or its licensors do not warrant that the design is production worthy. You should" at 125.758,-61.619 h1.14
  text "completely validate and test your design implementation to confirm the system functionality for your application." at 126.9,-64.481 h1.14
  text ".print_Scale" at 254.396,-64.502 h1.78
  text ".Application_BuildNumber" at 292.635,-64.502 h1.78
  text "1" at -16.207,-69.751 h1.78
  text "2" at 47.183,-69.751 h1.78
  text "3" at 110.412,-69.751 h1.78
  text "4" at 174.081,-69.751 h1.78
  text "5" at 237.556,-69.751 h1.78
  text "6" at 301.183,-69.751 h1.78
M10 Fab Notes:
  drawing of 189 lines, arcs and shapes, not listed
  text "DESIGN INFORMATION" at 279.504,123.788 h1.52
  text "MIN. TRACK WIDTH:" at 263.132,120.432 h1.52
  text "8" at 290.977,120.432 h1.52
  text "MIL" at 294.908,120.432 h1.52
  text "7.874" at 286.751,117.342 h1.52
  text "MIN. CLEARANCE:" at 263.132,117.28 h1.52
  text "MIL" at 294.908,117.28 h1.52
  text "MIN. VIA PAD SIZE:" at 263.132,114.127 h1.52
  text "24" at 290.215,114.127 h1.52
  text "MIL" at 294.908,114.127 h1.52
  text "0.05mm (2MIL)" at 280.785,110.827 h1.52
  text "MINIMUM ANNULAR RING" at 254.77,110.618 h1.52
  text "EXTERNAL" at 298.769,110.618 h1.52
  text "PER" at 259.85,107.821 h1.52
  text "IPC-D-275 CLASS 2 LEVEL C" at 265.438,107.821 h1.52
  text "MIL, HOLES" at 303.239,105.269 h1.52
  text "+/-" at 293.27,105.051 h1.52
  text "+/-" at 314.962,105.051 h1.52
  text "REGISTRATION TOLERANCES:" at 254.77,105.024 h1.52
  text "METAL" at 285.244,105.024 h1.52
  text "5" at 299.88,105.024 h1.52
  text "3" at 321.038,105.024 h1.52
  text "MIL" at 323.991,105.024 h1.52
  text "HOLE SIZE TOLERANCE (UNLESS OTHERWISE SPECIFIED):" at 254.77,102.527 h1.52
  text "+/-" at 314.962,102.454 h1.52
  text "3" at 321.038,102.427 h1.52
  text "MIL" at 323.991,102.427 h1.52
  text "MATERIAL:" at 252.871,98.931 h1.52
  text "FR-4 High Tg" at 277.926,95.666 h1.52
  text "X" at 274.258,95.463 h1.52
  text "FR-408" at 263.564,95.348 h1.52
  text "OTHER" at 301.359,95.348 h1.52
  text "62 MIL (1.6mm) +/-10%" at 271.695,91.715 h1.52
  text "X" at 268.644,91.653 h1.52
  text "THICKNESS:" at 254.77,91.507 h1.52
  text "OTHER" at 304.331,91.507 h1.52
  text "TOLERANCE:" at 254.77,87.993 h1.52
  text "X" at 276.315,87.993 h1.52
  text "ANSI IPC-6012 TYPE 3 CLASS 2" at 280.837,87.993 h1.52
  text "OTHER +/-" at 280.836,84.331 h1.52
  text "BOW & TWIST:" at 254.77,80.643 h1.52
  text "X" at 276.315,80.643 h1.52
  text "ANSI IPC-6012 TYPE 3 CLASS 2" at 280.837,80.643 h1.52
  text "OTHER +/-" at 280.836,76.917 h1.52
  text "DRILLING:" at 252.871,73.599 h1.52
  text "NC_DRILL FILES" at 297.6,70.928 h1.52
  text "REFERENCE:" at 254.77,70.828 h1.52
  text "X" at 271.464,70.825 h1.52
  text "AS SHOWN" at 275.985,70.828 h1.52
  text "X" at 294.349,70.828 h1.52
  text "OTHER" at 305.169,67.214 h1.52
  text "PTH COPPER THICKNESS:" at 254.762,67.125 h1.52
  text "X" at 283.698,67.125 h1.52
  text "20-30 um" at 286.949,67.125 h1.52
  text "BOARD FINISH:" at 252.871,63.376 h1.52
  text "SILKSCREEN:" at 256.813,60.579 h1.52
  text "X" at 281.141,60.579 h1.52
  text "TOP" at 284.113,60.579 h1.52
  text "X" at 294.095,60.579 h1.52
  text "BOTTOM" at 297.092,60.579 h1.52
  text "SILKSCREEN COLOR:" at 256.813,56.637 h1.52
  text "X" at 281.116,56.637 h1.52
  text "WHITE" at 284.113,56.637 h1.52
  text "OTHER" at 297.092,56.637 h1.52
  text "X" at 284.443,52.993 h1.52
  text "GREEN" at 287.44,52.993 h1.52
  text "OTHER" at 303.137,52.993 h1.52
  text "SOLDER RESIST COLOR:" at 256.813,52.819 h1.52
  text "X" at 284.443,49.075 h1.52
  text "MATTE" at 287.44,49.075 h1.52
  text "SEMI-GLOSS" at 303.126,49.059 h1.52
  text "IMMERSION GOLD (ENIG)" at 279.82,44.687 h1.52
  text "ENEPIG" at 313.794,44.503 h1.52
  text "SURFACE FINISH:" at 252.871,44.478 h1.52
  text "X" at 275.299,44.478 h1.52
  text "IMM. TIN/SILVER OR EQUIV" at 261.241,40.99 h1.52
  text "OTHER" at 297.6,40.89 h1.52
  text "ARRAY/PANEL:" at 252.871,36.944 h1.52
  text "CUT AND TRIM PER M1 BOARD OUTLINE" at 279.82,36.735 h1.52
  text "N.C. ROUTE" at 279.82,33.281 h1.52
  text "X" at 297.295,33.281 h1.52
  text "V. SCORE" at 301.817,33.281 h1.52
  text "CERTIFICATION:" at 252.871,30.001 h1.52
  text "MATERIALS AND WORKMANSHIP FOR ALL PCBS" at 271.286,30.001 h1.52
  text "TO MEET OR EXCEED THE REQUIREMENTS OF:" at 271.286,27.612 h1.52
  text "X" at 262.078,24.345 h1.52
  text "ANSI IPC-A-600F CLASS ->" at 265.33,24.345 h1.52
  text "X" at 307.189,24.345 h1.52
  text "2" at 309.983,24.345 h1.52
  text "1" at 301.982,24.307 h1.52
  text "3" at 318.974,24.307 h1.52
  text "X" at 282.703,20.594 h1.52
  text "RoHS" at 285.954,20.594 h1.52
  text "OTHER" at 302.322,20.594 h1.52
  text "PER ORDER" at 312.407,20.594 h1.52
  text "ALL BOARDS MUST MEET OR EXCEED UL94-V0 REQUIREMENTS." at 253.57,16.687 h1.52
  text "PCB MUST BEAR THE UL94V-0 UL REGISTERED MATERIAL ID NUMBER" at 253.57,13.739 h1.52
  text "ADDITIONAL REQUIREMENTS:" at 252.871,9.435 h1.52
  text "MICROSECTION:" at 254.77,6.714 h1.52
  text "YES" at 277.776,6.714 h1.52
  text "REQUIRED" at 299.658,3.048 h1.52
  text "BARE BOARD ELEC. TEST:" at 254.77,2.976 h1.52
  text "NONE" at 287.936,2.976 h1.52
  text "X" at 296.66,2.976 h1.52
  text "PER ORDER" at 314.694,2.976 h1.52
  text "XX MIL VIAS REQUIRE NON-CONDUCTIVE FILL AND PLANARIZE" at 259.041,-2.23 h1.5
  text "XX MIL VIAS REQUIRE CONDUCTIVE FILL AND PLANARIZE" at 259.244,-4.871 h1.52
  text "OUTER XX MIL TRACES REQUIRE 50 OHM SINGLE-ENDED IMPEDANCE" at 259.219,-9.021 h1.47
  text "LAYER 2 & 3 (INNER LAYERS) XX MIL WIDE, XX MIL SPACE / TRACES REQUIRE 100 OHM DIFFERENTIAL IMPEDANCE" at 259.016,-15.008 h1.52
  text ".Layer_Name" at -20.343,-59.464 h1.52
M11 Gerber Information:
  lines w0.254: -42.416,-61.285 125.224,-61.285 ; -42.416,-56.12 125.275,-56.12 ; -42.416,-50.955 -42.416,-66.449 59.311,-66.449 125.275,-66.449 125.275,-50.955 -42.403,-50.955 -42.403,-66.449 -2.386,-66.449 ; 20.195,-66.449 20.195,-50.955 ; 52.377,-56.12 52.377,-50.955 ; 73.713,-56.12 73.713,-50.955 ; 89.512,-66.614 89.512,-61.463
  text "ALL ARTWORK VIEWED FROM TOP SIDE" at -40.803,-54.312 h1.52
  text "BOARD #:" at 22.1,-54.312 h1.52
  text ".PRJ_Number" at 35.956,-54.312 h1.52
  text "REV:" at 57.406,-54.312 h1.52
  text ".PCB_Rev" at 64.81,-54.312 h1.52
  text "SVN REV:" at 78.691,-54.312 h1.52
  text ".VersionControl_RevNumber" at 91.544,-54.312 h1.52
  text "LAYER NAME =" at -40.803,-59.464 h1.52
  text "TID #:" at 22.1,-59.477 h1.52
  text ".TID" at 35.956,-59.477 h1.52
  text "PLOT NAME =" at -40.803,-64.693 h1.52
  text ".plot_File_Name" at -20.343,-64.693 h1.52
  text "GENERATED    :" at 22.151,-64.693 h1.52
  text ".Print_Date" at 44.236,-64.693 h1.52
  text ".Print_Time" at 62.753,-64.693 h1.52
  text "TEXAS INSTRUMENTS" at 94.871,-64.693 h1.52
M12 Stackup:
  drawing of 298 lines, arcs and shapes, not listed
  text "Layer" at 214.469,162.365 h1.52
  text "Name" at 224.881,162.365 h1.52
  text "Material" at 248.497,162.365 h1.52
  text "Thickness" at 270.335,162.365 h1.52
  text "Constant" at 286.841,162.365 h1.52
  text "Board Layer Stack" at 301.315,162.365 h1.52
  text "Top Overlay" at 224.881,159.317 h1.52
  text "Top Solder" at 224.881,156.269 h1.52
  text "Solder Resist" at 248.497,156.269 h1.52
  text "0.40mil" at 270.335,156.269 h1.52
  text "3.5" at 286.841,156.269 h1.52
  text "1" at 214.469,153.221 h1.52
  text "Top Layer" at 224.881,153.221 h1.52
  text "CF-005" at 248.497,153.221 h1.52
  text "2.76mil" at 270.335,153.221 h1.52
  text "Dielectric 1" at 224.881,150.173 h1.52
  text "PP-006" at 248.497,150.173 h1.52
  text "2.80mil" at 270.335,150.173 h1.52
  text "4.1" at 286.841,150.173 h1.52
  text "2" at 214.469,147.125 h1.52
  text "Layer 1" at 224.881,147.125 h1.52
  text "CF-005" at 248.497,147.125 h1.52
  text "2.76mil" at 270.335,147.125 h1.52
  text "Dielectric1" at 224.881,144.077 h1.52
  text "FR-4 High Tg" at 248.497,144.077 h1.52
  text "59.20mil" at 270.335,144.077 h1.52
  text "4.8" at 286.841,144.077 h1.52
  text "3" at 214.469,141.029 h1.52
  text "Layer 2" at 224.881,141.029 h1.52
  text "CF-005" at 248.497,141.029 h1.52
  text "2.76mil" at 270.335,141.029 h1.52
  text "Dielectric 2" at 224.881,137.981 h1.52
  text "PP-006" at 248.497,137.981 h1.52
  text "2.80mil" at 270.335,137.981 h1.52
  text "4.1" at 286.841,137.981 h1.52
  text "4" at 214.469,134.933 h1.52
  text "Bottom Layer" at 224.881,134.933 h1.52
  text "CF-005" at 248.497,134.933 h1.52
  text "2.76mil" at 270.335,134.933 h1.52
  text "Bottom Solder" at 224.881,131.885 h1.52
  text "Solder Resist" at 248.497,131.885 h1.52
  text "0.40mil" at 270.335,131.885 h1.52
  text "3.5" at 286.841,131.885 h1.52
  text "Bottom Overlay" at 224.881,128.837 h1.52
  text ".Layer_Name" at -20.343,-59.464 h1.52
M13 Component Bodies Top:
  text ".Layer_Name" at -20.343,-59.464 h1.52
M14 Component Bodies Bottom:
  text ".Layer_Name" at -20.343,-59.464 h1.52
M15 Courtyards Top:
  text ".Layer_Name" at -20.343,-59.464 h1.52
M16 Courtyards Bottom:
  text ".Layer_Name" at -20.343,-59.464 h1.52
Drill Drawing:
  lines w0.254: 143.254,47.819 143.956,47.117 144.658,47.819 143.956,48.52 143.254,47.819
  lines w0.305: 141.982,46.17 224.062,46.17 ; 141.982,49.327 224.062,49.327 ; 150.564,43.012 150.564,52.485 ; 158.997,43.012 158.997,52.485 ; 175.165,43.012 175.165,52.485 ; 181.747,43.012 181.747,52.485 ; 191.276,43.012 191.276,52.485 ; 209.674,43.012 209.674,52.485 ; 141.982,43.012 224.062,43.012 224.062,52.485 141.982,52.485 141.982,43.012
  text "Symbol" at 143.877,50.275 h1.83
  text "Quantity" at 151.511,50.275 h1.83
  text "Finished Hole Size" at 159.944,50.275 h1.83
  text "Plated" at 176.113,50.275 h1.83
  text "Hole Type" at 182.695,50.275 h1.83
  text "Drill Layer Pair" at 192.224,50.275 h1.83
  text "Hole Tolerance" at 210.622,50.275 h1.83
  text "303" at 151.511,47.117 h1.52
  text "8.00mil (0.203mm)" at 159.944,47.117 h1.52
  text "PTH" at 176.113,47.117 h1.52
  text "Round" at 182.695,47.117 h1.52
  text "Top Layer - Bottom Layer" at 192.224,47.117 h1.52
  text "303 Total" at 151.511,43.959 h1.52
  text ".Layer_Name" at -20.343,-59.464 h1.52
M17 Embedded Cavity:
  text ".Layer_Name" at -20.343,-59.464 h1.52
M18 Embedded Assembly:
  text ".Layer_Name" at -20.343,-59.464 h1.52
M19 Embedded Keepout:
  text ".Layer_Name" at -20.343,-59.464 h1.52

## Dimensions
0,31 to 1,0 on M2 Board Dimensions
0,4 to 22.4,4 on M2 Board Dimensions
-34.999,-47.818 to -9.599,-47.818 on M2 Board Dimensions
